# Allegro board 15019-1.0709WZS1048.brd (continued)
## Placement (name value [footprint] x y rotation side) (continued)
NOREF#2  *  [unnamed]  40.67 23.11 0 top
NOREF#3  -  [#2]  -10 0 0 top
NOREF#4  *  [unnamed]  62.77 66.55 0 top
NOREF#5  *  [unnamed]  72.55 202.69 0 top
NOREF#6  -  [unnamed]  11.57 4.95 0 top
NOREF#7  -  [unnamed]  184.44 225.3 0 top
NOREF#8  *  [unnamed]  169.06 9.9 0 top
NOREF#9  -  [#2]  96.43 126.87 0 top
NOREF#10  -  [unnamed]  149 223.77 0 top
NOREF#11  -  [#2]  -310 0 0 top
NOREF#12  -  [#2]  0 100.97 0 top
NOREF#13  *  [unnamed]  7.78 219.33 0 top
NOREF#14  -  [#2]  -10 0 0 top
NOREF#15  -  [unnamed]  6.64 225.3 0 top
NOREF#16  -  [#2]  -10 0 0 top
NOREF#17  -  [#2]  105.19 194.31 0 top
NOREF#18  -  [#2]  133.89 208.03 0 top
NOREF#19  *  [unnamed]  157.46 223.44 0 top
NOREF#20  *  [unnamed]  180.24 219.05 0 top
NOREF#21  *  [unnamed]  166.66 27.56 0 top
NOREF#22  -  [unnamed]  178.22 223.03 0 top
NOREF#23  *  [unnamed]  7.46 5.42 0 top
NOREF#24  -  [#2]  152.81 98.04 0 top
NOREF#25  -  [unnamed]  171.63 4.95 0 top
NOREF#26  -  [#2]  -10 0 0 top
NOREF#27  -  [unnamed]  6.64 9.4 0 top
NOREF#28  -  [#2]  120.05 156.34 90 bottom
NOREF#29  *  [unnamed]  40.17 24.64 180 bottom
NOREF#30  -  [#2]  178.7 28.65 90 bottom
NOREF#31  *  [unnamed]  169.06 9.9 180 bottom
NOREF#32  *  [unnamed]  45.37 223.77 180 bottom
NOREF#33  *  [unnamed]  157.46 223.44 180 bottom
NOREF#34  *  [unnamed]  7.46 5.42 180 bottom
NOREF#35  *  [unnamed]  180.24 219.05 180 bottom
NOREF#36  *  [unnamed]  49.56 123.7 180 bottom
PC1  SC1U10V2KX-1DLGP  [C402H22]  124.87 208.41 90 bottom
PC34  SCD1U10V2KX-5GP  [C402H22]  101.25 64.64 90 bottom
PC48  SCD1U10V2KX-5GP  [C402H22]  17.43 157.35 270 bottom
PC49  SC1U16V3KX-4DLGP  [C603H36]  164.5 207.9 90 top
PC50  SC10U6D3V5KX-4DLGP-U  [C805H58]  154.21 207.52 270 top
PC51  SCD1U50V3KX-DL-GP  [C603H35]  152.69 205.87 90 top
PC52  SC10U6D3V5KX-4DLGP-U  [C805H58]  158.91 207.14 270 top
PC96  SCD1U16V2KX-3DLGP  [C402H22]  105.95 6.99 0 top
PC126  SC22P50V2JN-4GP  [C402H22]  157.26 194.31 90 top
PC140  SC1U10V2KX-1DLGP  [C402H22]  39.66 8 0 bottom
PC2127  SC470P50V2KX-3DLGP  [C402H22]  152.81 17.02 270 top
PC4301  SC10P50V2JN-4DLGP  [C402H22]  35.21 64.39 90 top
PC4302  SCD1U50V3KX-DL-GP  [C603H35]  36.48 71.63 180 top
PC4303  SC2200P50V2KX-2DLGP  [C402H22]  36.48 71.5 0 bottom
PC4304  SC470P50V2KX-3DLGP  [C402H22]  35.21 61.34 90 top
PC4305  SC10P50V2JN-4DLGP  [C402H22]  35.21 65.28 90 top
PC4401  SC10U25V5KX-DL-GP  [C805H58]  34.86 71.27 0 bottom
PC4402  SCD1U50V3KX-DL-GP  [C603H35]  57.69 61.34 270 bottom
PC4403  SCD1U50V3KX-DL-GP  [C603H35]  59.09 62.61 270 bottom
PC4404  SCD1U50V3KX-DL-GP  [C603H35]  56.29 62.61 90 bottom
PC4405  SCD1U25V2KX-1-DL-GP  [C402H22]  42.63 54.79 90 top
PC4406  SC10U25V5KX-DL-GP  [C805H58]  43.21 53.34 270 bottom
PC4407  SC10U25V5KX-DL-GP  [C805H58]  43.21 53.34 90 top
PC4408  SC1U25V5KX-3-GP  [C805H58]  55.53 58.93 90 bottom
PC4426  SC1U25V3KX-1-GP  [C603H36]  73.06 53.72 90 bottom
PC4601  SC1KP50V2KX-1DLGP  [C402H22]  24.29 222.63 270 bottom
PC4602  SC1U25V3KX-1-DLGP  [C603H36]  32.01 220.47 0 top
PC4603  SC3300P50V2KX-1DLGP  [C402H22]  22.64 217.17 180 bottom
PC4605  SC1KP50V2KX-1DLGP  [C402H22]  34.96 224.03 0 bottom
PC4606  SC1KP50V2KX-1DLGP  [C402H22]  27.34 216.92 90 top
PC4607  SCD1U16V2KX-3DLGP  [C402H22]  26.83 224.03 180 bottom
PC4608  SC2D2U10V3KX-1DLGP-U  [C603H36]  31.4 215.52 180 top
PC4609  SCD01U50V2KX-1DLGP  [C402H22]  27.34 217.81 270 top
PC4610  SC330P50V2KX-3-DL-GP  [C402H22]  38.51 221.62 90 bottom
PC4611  SC2200P50V2KX-2DLGP  [C402H22]  38.51 219.58 90 bottom
PC4612  SC10P50V2JN-4DLGP  [C402H22]  36.99 220.09 180 bottom
PC4613  SC330P50V2KX-3-DL-GP  [C402H22]  37.5 215.52 90 bottom
PC4614  SCD01U50V2KX-1DLGP  [C402H22]  33.05 220.73 0 top
PC4615  SC680P50V2KX-2DLGP  [C402H22]  23.15 214.63 90 bottom
PC4616  SCD01U50V2KX-1DLGP  [C402H22]  33.05 218.69 270 top
PC4617  SC680P50V2KX-2DLGP  [C402H22]  37.5 214.63 270 bottom
PC4618  SC1KP50V2KX-1DLGP  [C402H22]  23.15 213.74 270 bottom
PC4619  SCD1U16V2KX-3DLGP  [C402H22]  35.97 220.73 180 top
PC4621  SC330P50V2KX-3-DL-GP  [C402H22]  21.75 221.11 180 bottom
PC4622  SC1KP50V2KX-1DLGP  [C402H22]  33.05 216.03 270 top
PC4623  SCD047U16V2KX-1-DL-GP  [C402H22]  37.5 214.63 90 top
PC4624  SC3300P50V2KX-1DLGP  [C402H22]  38.01 218.06 180 bottom
PC4626  SC2200P50V2KX-2DLGP  [C402H22]  22.26 218.57 270 bottom
PC4627  SC10P50V2JN-4DLGP  [C402H22]  23.66 219.07 180 bottom
PC4628  SCD047U16V2KX-1-DL-GP  [C402H22]  23.15 213.74 90 top
PC4701  SC10U25V6KX-4DL-GP  [C1206H71]  41.56 199.01 90 bottom
PC4702  SC10U25V6KX-4DL-GP  [C1206H71]  41.56 201.29 270 top
PC4703  SCD1U50V3KX-DL-GP  [C603H35]  41.44 199.52 270 top
PC4704  SCD22U25V3KX-DL-GP  [C603H36]  32.93 209.42 0 bottom
PC4705  SC10U25V6KX-4DL-GP  [C1206H71]  41.56 201.29 90 bottom
PC4706  SC1KP50V2KX-1DLGP  [C402H22]  42.45 195.2 180 top
PC4707  SC10U25V6KX-4DL-GP  [C1206H71]  27.85 201.19 270 bottom
PC4708  SC10U25V6KX-4DL-GP  [C1206H71]  27.85 201.17 90 top
PC4709  SCD1U50V3KX-DL-GP  [C603H35]  27.85 199.39 90 top
PC4710  SCD22U25V3KX-DL-GP  [C603H36]  28.74 209.42 0 bottom
PC4711  SC10U25V6KX-4DL-GP  [C1206H71]  27.85 199.01 270 bottom
PC4712  SC1KP50V2KX-1DLGP  [C402H22]  27.08 195.2 180 top
PC4713  SCD1U50V3KX-DL-GP  [C603H35]  29.75 164.59 90 top
PC4801  SC10U25V6KX-4DL-GP  [C1206H71]  26.07 157.86 0 top
PC4802  SCD1U16V2KX-3DLGP  [C402H22]  40.67 152.02 270 top
PC4803  SC1U10V2KX-1DLGP  [C402H22]  23.07 155.68 90 top
PC4804  SC1KP50V2KX-1DLGP  [C402H22]  17.43 156.46 270 bottom
PC4805  SC18P50V2JN-1DLGP  [C402H22]  13.62 154.18 180 top
PC4806  SCD1U50V3KX-DL-GP  [C603H35]  24.29 158.12 180 top
PC4807  SC1KP50V2KX-1DLGP  [C402H22]  33.18 156.84 270 top
PC4808  SC10U25V6KX-4DL-GP  [C1206H71]  26.07 157.86 180 bottom
PC4901  SCD01U50V2KX-1DLGP  [C402H22]  123.22 8.97 90 bottom
PC4902  SC10U25V6KX-4DL-GP  [C1206H71]  121.11 7.11 0 bottom
PC4903  SCD1U50V3KX-DL-GP  [C603H35]  115.6 10.16 180 top
PC4904  SC10U25V6KX-4DL-GP  [C1206H71]  120.48 23.24 180 bottom
PC4905  SCD01U50V2KX-1DLGP  [C402H22]  123.3 21.11 90 bottom
PC4906  SC1U10V2KX-1DLGP  [C402H22]  114.84 13.97 90 top
PC4907  SCD1U50V3KX-DL-GP  [C603H35]  112.05 6.22 0 top
PC4908  SCD1U50V3KX-DL-GP  [C603H35]  112.56 17.14 0 top
PC4909  SC1U10V2KX-1DLGP  [C402H22]  132.62 5.97 0 top
PC4910  SC1U10V2KX-1DLGP  [C402H22]  132.62 22.99 180 top
PC4911  SC22P50V2JN-4DLGP  [C402H22]  106.97 10.03 0 top
PC4912  SC1U16V3KX-4DLGP  [C603H36]  106.08 15.75 270 top
PC4913  SC22P50V2JN-4DLGP  [C402H22]  106.97 14.1 0 top
PC4914  SC4D7U6D3V3KX-DLGP  [C603H36]  115.22 14.99 270 top
PC4915  SC1500P50V3KX-DLGP  [C603H36]  122.92 20.09 90 bottom
PC4916  SC1500P50V3KX-DLGP  [C603H36]  122.84 10.01 90 bottom
PC4917  SC18P50V2JN-1DLGP  [C402H22]  106.46 14.1 90 bottom
PC4918  SC18P50V2JN-1DLGP  [C402H22]  106.46 10.03 90 bottom
PC5001  SC10U10V5KX-2DLGP  [C805H50]  136.05 80.77 270 top
PC5003  SC1KP50V2KX-1DLGP  [C402H22]  147.1 80.39 270 top
PC5009  SC1U10V2KX-1DLGP  [C402H22]  146.46 76.96 90 top
PC5010  SCD1U50V3KX-DL-GP  [C603H35]  144.31 83.57 0 top
PC5011  SC10U10V5KX-2DLGP  [C805H50]  137.32 83.95 180 top
PC5012  SC1U16V3KX-4DLGP  [C603H36]  143.29 104.01 0 top
PC5013  SC18P50V2JN-1DLGP  [C402H22]  139.99 74.04 90 top
PC5014  SCD033U25V3KX-DL-GP  [C603H36]  136.43 75.11 270 top
PC5016  SC10U10V5KX-2DLGP  [C805H50]  135.29 83.95 180 top
PC5017  SC1500P50V3KX-DLGP  [C603H36]  141.38 93.27 180 bottom
PC5018  SC1U10V2KX-1DLGP  [C402H22]  146.46 76.07 90 top
PC5019  SCD1U50V3KX-DL-GP  [C603H35]  138.84 92.58 270 bottom
PC5020  SC10U25V6KX-4DL-GP  [C1206H71]  138.84 88.52 270 bottom
PC5021  SC10U25V6KX-4DL-GP  [C1206H71]  138.84 90.81 270 bottom
PC5022  SC10U25V6KX-4DL-GP  [C1206H71]  138.84 88.52 90 top
PC5202  SC1500P50V3KX-DLGP  [C603H36]  107.22 66.8 270 bottom
PC5203  SC22P50V2JN-4DLGP  [C402H22]  101.25 61.59 90 top
PC5204  SC1U10V2KX-1DLGP  [C402H22]  101.25 64.64 270 top
PC5205  SC22U6D3V3MX-1-DL-GP  [C603H40]  103.03 77.34 180 top
PC5209  SC10U25V6KX-4DL-GP  [C1206H71]  106.97 58.55 90 top
PC5210  SC22U6D3V3MX-1-DL-GP  [C603H40]  104.3 77.34 180 top
PC5211  SC22U6D3V3MX-1-DL-GP  [C603H40]  105.57 77.34 180 top
PC5212  SC22U6D3V3MX-1-DL-GP  [C603H40]  101.76 77.34 180 top
PC5213  SCD1U16V2KX-3DLGP  [C402H22]  100.62 77.34 180 top
PC5214  SC10U25V6KX-4DL-GP  [C1206H71]  106.97 60.83 90 top
PC5217  SCD1U25V2KX-1-DL-GP  [C402H22]  101.25 66.67 90 top
PC5232  SCD01U50V2KX-1DLGP  [C402H22]  65.44 57.53 270 bottom
PC5233  SC1U10V2KX-1DLGP  [C402H22]  55.63 53.34 0 bottom
PC5234  SCD1U50V3KX-DL-GP  [C603H35]  55.91 57.23 270 bottom
PC5235  SC1KP50V2KX-1DLGP  [C402H22]  44.94 70.15 180 top
PC5236  SCD1U50V3KX-DL-GP  [C603H35]  60.99 49.78 270 bottom
PC5237  SC470P50V2KX-3DLGP  [C402H22]  58.86 51.99 180 bottom
PC5238  SCD1U25V2KX-1-DL-GP  [C402H22]  62.77 49.28 180 bottom
PC5239  SC220P50V2KX-3DLGP  [C402H22]  65.44 56.52 270 bottom
PC5240  SC10U25V5KX-DL-GP  [C805H58]  34.86 71.27 180 top
PC5241  SC10U25V5KX-DL-GP  [C805H58]  38.13 64.14 0 top
PC5242  SCD1U50V3KX-DL-GP  [C603H35]  39.78 64.26 0 top
PC5243  SC1U16V3KX-4DLGP  [C603H36]  18.96 147.83 270 top
PC5244  SC100P50V2JN-3DLGP  [C402H22]  31.28 143.26 0 top
PC5245  SCD1U10V2KX-5GP  [C402H22]  22 138.68 0 top
PC5246  SC1U16V3KX-4DLGP  [C603H36]  32.42 146.81 180 top
PC5247  SC10U10V5KX-2DLGP  [C805H50]  24.93 148.72 180 top
PC5248  SC10U10V5KX-2DLGP  [C805H50]  30.77 146.69 180 top
PC5401  SC10U25V6KX-4DL-GP  [C1206H71]  49.31 214.88 90 top
PC5402  SC10U25V6KX-4DL-GP  [C1206H71]  49.31 217.42 90 top
PC5403  SCD1U50V3KX-DL-GP  [C603H35]  49.94 216.03 270 bottom
PC5404  SC10U25V6KX-4DL-GP  [C1206H71]  42.22 212.57 270 top
PC5405  SC1KP50V2KX-1DLGP  [C402H22]  52.99 221.11 0 bottom
PC5411  SCD22U25V3KX-DL-GP  [C603H36]  71.66 213.74 270 bottom
PC5413  SC1KP50V2KX-1DLGP  [C402H22]  77.5 218.69 0 top
PC5414  SC1KP50V2KX-1DLGP  [C402H22]  75.09 222.88 180 bottom
PC5415  SC330P50V2KX-3-DL-GP  [C402H22]  82.84 223.9 180 bottom
PC5416  SC10P50V2JN-4DLGP  [C402H22]  81.95 222.88 180 bottom
PC5417  SC2200P50V2KX-2DLGP  [C402H22]  81.06 222.88 180 bottom
PC5418  SC1KP50V2KX-1DLGP  [C402H22]  84.74 219.2 180 bottom
PC5419  SC3300P50V2KX-1DLGP  [C402H22]  79.66 222.38 90 bottom
PC5420  SC1U25V3KX-1-DLGP  [C603H36]  85.63 214.38 270 bottom
PC5421  SC2D2U16V3KX-DL-GP  [C603H36]  76.49 209.17 180 bottom
PC5422  SCD1U10V2KX-5DLGP  [C402H22]  81.57 218.69 180 top
PC5423  SCD01U25V2KX-3DLGP  [C402H22]  79.54 218.69 180 top
PC5424  SCD01U25V2KX-3DLGP  [C402H22]  82.71 209.55 180 bottom
PC5425  SC680P50V2KX-2DLGP  [C402H22]  74.2 222.88 0 bottom
PC5426  SCD047U16V2KX-1-DL-GP  [C402H22]  71.66 221.49 270 bottom
PC5427  SC1U16V3KX-4DLGP  [C603H36]  154.97 208.79 270 bottom
PC5428  SC1U16V3KX-4DLGP  [C603H36]  154.97 213.11 270 bottom
PC5429  SC1U16V3KX-4DLGP  [C603H36]  151.04 212.85 90 bottom
PD4401  RB520SM-30T2R-GP  [D1608-035030AKH28]  54.24 54.48 0 bottom
PD4405  1N4148WS-7-F-GP  [SOD323AKH42]  72.8 63.75 270 bottom
PG4701  COPPER-CLOSE-GP-U  [CON2C-U]  40.29 185.17 0 top
PG4702  COPPER-CLOSE-GP-U  [CON2C-U]  40.29 178.82 180 top
PG4703  COPPER-CLOSE-GP-U  [CON2C-U]  29.12 185.17 0 top
PG4704  COPPER-CLOSE-GP-U  [CON2C-U]  29.12 178.82 180 top
PG4801  GAP-CLOSE-PWR-3-GP  [GAP-CLOSE-PWR-3]  40.67 151 0 top
PG4901  GAP-CLOSE-PWR-3-GP  [GAP-CLOSE-PWR-3]  115.1 13.08 0 top
PG4902  GAP-CLOSE-PWR-3-GP  [GAP-CLOSE-PWR-3]  136.94 5.08 90 top
PG4903  GAP-CLOSE-PWR-3-GP  [GAP-CLOSE-PWR-3]  136.94 24.26 90 top
PG4904  GAP-CLOSE-PWR-3-GP  [GAP-CLOSE-PWR-3]  114.71 16.13 0 top
PG4905  GAP-CLOSE-PWR-3-GP  [GAP-CLOSE-PWR-3]  58.58 48.26 0 top
PG4906  GAP-CLOSE-PWR-3-GP  [GAP-CLOSE-PWR-3]  47.66 65.79 270 bottom
PG4907  GAP-CLOSE-PWR-3-GP  [GAP-CLOSE-PWR-3]  58.58 47.32 0 top
PG4908  GAP-CLOSE-PWR-3-GP  [GAP-CLOSE-PWR-3]  49.18 65.79 270 bottom
PG5001  GAP-CLOSE-PWR-3-GP  [GAP-CLOSE-PWR-3]  134.15 107.7 270 top
PG5205  -  [GAP-CLOSE-PWR]  103.92 58.67 0 top
PG5210  -  [GAP-CLOSE-PWR]  103.92 57.91 0 top
PG5211  GAP-CLOSE-PWR-3-GP  [GAP-CLOSE-PWR-3]  99.35 76.58 180 top
PG5212  GAP-CLOSE-PWR-3-GP  [GAP-CLOSE-PWR-3]  106.97 76.58 0 top
PG5401  COPPER-CLOSE-GP-U  [CON2C-U]  59.22 211.46 0 top
PG5402  COPPER-CLOSE-GP-U  [CON2C-U]  59.22 205.1 180 top
PG9001  GAP-CLOSE-PWR-3-GP  [GAP-CLOSE-PWR-3]  59.27 98.09 0 top
PL4301  MLVS0402M04-GP-U  [L402H24]  35.21 62.36 90 top
PL4302  MLVS0402M04-GP-U  [L402H24]  35.21 66.29 90 top
PL4303  MLVS0402M04-GP-U  [L402H24]  35.21 63.37 90 top
PL4701  IND-D36UH-19-GP  [L115100-2H158]  40.29 181.99 0 top
PL4702  IND-D36UH-19-GP  [L115100-2H158]  29.12 181.99 0 top
PL4802  IND-1D5UH-53-GP  [L686647H119]  39.78 156.34 0 top
PL4903  IND-3D3UH-116-GP-U  [L686647-127318H119]  128.56 10.67 270 top
PL4904  IND-2D2UH-122-GP  [L686647H119]  128.68 18.29 0 top
PL5001  IND-D68UH-36-GP  [L686647H119]  138.84 102.23 90 top
PL5003  IND-5D6UH-48-GP-U1  [L7066-1830-UH119]  42.71 61.47 0 bottom
PL5202  IND-2D2UH-122-GP  [L686647H119]  103.16 71.6 90 top
PL5401  IND-D36UH-19-GP  [L115100-2H158]  59.22 208.28 0 top
PQ4204  PDTC124EU-1-GP  [SOT323CBE2D2H44]  67.47 36.96 270 bottom
PQ4205  PDTA124EU-1-GP  [SOT323CBE2D2H44]  67.34 33.4 180 bottom
PQ4206  2N7002K-2-GP  [SOT23DGS2D4H44]  67.22 40.39 180 bottom
PQ4406  2N7002KDW-GP  [SOT-363H44]  73.44 56.13 0 bottom
PQ4408  2N7002K-2-GP  [SOT23DGS2D4H44]  71.69 63.98 0 top
PQ4409  MMBT3906-4-GP  [SOT23CBE2D4H44]  72.55 60.83 0 bottom
PQ5003  2N7002A-7-GP  [SOT23DGS2D4H48]  71.69 67.79 0 top
PQ5004  2N7002A-7-GP  [SOT23DGS2D4H48]  66.81 63.96 0 top
PQ5005  NTJD512NT1G-GP  [SOT-363H44]  48.55 38.99 0 top
PQ5006  2N7002KDW-GP  [SOT-363H44]  62.39 65.28 0 bottom
PR24  0R0402-PAD-2-GP  [0R0402-PAD-1]  33.94 224.03 0 bottom
PR57  10KR2F-2-GP  [R402H16]  101.25 62.61 270 bottom
PR62  10KR2F-2-GP  [R402H16]  101.25 60.58 90 top
PR83  10R2F-L-GP  [R402H14]  17.18 163.45 90 top
PR190  10KR2J-3-GP  [R402H16]  106.97 6.99 0 top
PR4210  1KR2J-1-GP  [R402H16]  69.5 39.5 180 bottom
PR4214  3K3R6J-GP  [R1206H28]  67.22 30.23 270 bottom
PR4412  47KR2F-GP  [R402H16]  65.44 58.55 270 bottom
PR4413  100KR2F-L1-GP  [R402H16]  73.57 52.2 0 bottom
PR4425  3K3R2J-3-GP  [R402H16]  66.86 53.01 0 bottom
PR4426  3K3R2J-3-GP  [R402H16]  66.86 54.91 180 bottom
PR4427  100KR2J-1-GP  [R402H16]  65.95 60.83 90 bottom
PR4431  100KR2J-1-GP  [R402H16]  75.34 61.85 90 bottom
PR4433  1MR2J-1-GP  [R402H16]  75.34 60.83 270 bottom
PR4450  10KR2F-2-GP  [R402H16]  72.55 52.2 180 bottom
PR4451  680KR2F-GP  [R402H16]  75.34 59.82 270 bottom
PR4455  0R2J-2-GP  [R402H16]  75.47 56.64 0 bottom
PR4458  0R2J-2-GP  [R402H16]  74.2 65.41 270 bottom
PR4462  0R2J-2-GP  [R402H16]  73.06 58.42 270 bottom
PR4601  1KR2F-3-GP  [R402H16]  23.66 217.17 180 bottom
PR4602  2R2F-GP  [R402H16]  32.93 224.08 0 top
PR4603  10KR2F-2-GP  [R402H16]  24.67 209.17 180 bottom
PR4604  0R0402-PAD-2-GP  [0R0402-PAD-1]  23.78 224.03 0 bottom
PR4605  61K9R2F-GP  [R402H16]  27.85 224.03 180 bottom
PR4606  0R0402-PAD-2-GP  [0R0402-PAD-1]  24.8 224.03 0 bottom
PR4608  10KR2F-2-GP  [R402H16]  37.5 213.61 90 top
PR4609  27K4R2F-GP  [R402H16]  37.5 216.53 270 bottom
PR4610  54K9R2F-L-GP  [R402H16]  31.91 224.03 180 bottom
PR4611  100R2J-2-GP  [R402H14]  65.44 186.06 90 top
PR4612  10R2F-L-GP  [R402H14]  37.5 212.6 270 bottom
PR4613  NTC-100K-10-GP-U  [NTC-402H22-U]  51.21 196.34 180 top
PR4614  27K4R2F-GP  [R402H16]  27.34 218.82 90 top
PR4615  10KR2F-2-GP  [R402H16]  23.15 212.72 270 top
PR4616  1KR2F-3-GP  [R402H16]  36.36 222.66 270 top
PR4618  10R2F-L-GP  [R402H14]  23.15 211.71 90 bottom
PR4619  75KR2F-GP  [R402H16]  21.62 216.15 0 bottom
PR4620  165KR2F-GP  [R402H16]  23.15 215.65 90 top
PR4621  1KR2F-3-GP  [R402H16]  36.99 222.12 180 bottom
PR4622  49D9R2F-GP  [R402H16]  38.51 222.63 270 bottom
PR4623  8K2R2F-1-GP  [R402H16]  38.51 220.6 270 bottom
PR4624  10KR2F-2-GP  [R402H16]  28.86 224.03 180 bottom
PR4625  41K2R2F-GP  [R402H16]  38.26 213.61 270 bottom
PR4626  27K4R2F-GP  [R402H16]  23.15 215.65 90 bottom
PR4627  28K7R2F-GP  [R402H16]  33.05 217.04 270 top
PR4628  100R2J-2-GP  [R402H14]  65.44 187.2 90 top
PR4629  61K9R2F-GP  [R402H16]  34.96 220.73 180 top
PR4630  NTC-100K-10-GP-U  [NTC-402H22-U]  18.19 196.34 180 top
PR4631  0R2J-2-GP  [R402H16]  23.15 210.69 90 bottom
PR4632  10KR2F-2-GP  [R402H16]  29.88 224.03 180 bottom
PR4633  0R0402-PAD-2-GP  [0R0402-PAD-1]  37.5 211.58 270 bottom
PR4634  49D9R2F-GP  [R402H16]  23.15 221.62 90 bottom
PR4635  24KR2F-GP  [R402H16]  25.69 209.17 180 bottom
PR4636  1KR2F-3-GP  [R402H16]  23.15 220.6 90 bottom
PR4637  NTC-220K-GP-U  [NTC-402H22-U]  23.02 183.01 180 top
PR4638  1KR2F-3-GP  [R402H16]  36.99 218.06 180 bottom
PR4639  NTC-220K-GP-U  [NTC-402H22-U]  46.39 184.15 180 top
PR4640  75KR2F-GP  [R402H16]  39.02 218.06 0 bottom
PR4641  48D7KR2F-GP  [R402H16]  22.26 212.72 90 bottom
PR4642  0R0402-PAD-2-GP  [0R0402-PAD-1]  35.97 224.03 0 bottom
PR4643  100R2J-2-GP  [R402H14]  41.94 170.31 90 top
PR4644  300KR2F-GP  [R402H16]  37.5 216.53 270 top
PR4645  8K2R2F-1-GP  [R402H16]  22.26 219.58 90 bottom
PR4685  10R2F-L-GP  [R402H14]  72.17 222.88 0 bottom
PR4701  2D2R3-1-U-GP  [R603H22]  34.2 209.42 180 bottom
PR4702  2D2R6J-3-GP  [R1206H28]  42.96 191.9 180 top
PR4703  2D2R3-1-U-GP  [R603H22]  27.47 209.42 180 bottom
PR4704  2D2R6J-3-GP  [R1206H28]  26.45 191.9 180 top
PR4802  75KR2F-GP  [R402H16]  14.13 157.73 90 top
PR4803  11K8R2F-GP  [R402H16]  14.64 154.18 180 top
PR4805  10KR2J-3-GP  [R402H16]  15.53 159.38 0 top
PR4806  2D2R5J-1-GP  [R805H24]  30.39 156.34 270 top
PR4807  470KR2F-GP  [R402H16]  16.77 153.97 270 top
PR4812  2D2R3-1-U-GP  [R603H22]  23.53 160.15 90 top
PR4814  -  [0R0805-PAD]  25.31 163.07 90 top
PR4815  -  [0R0805-PAD]  25.31 165.1 90 top
PR4816  33KR2F-GP  [R402H16]  14.13 155.7 270 top
PR4901  100KR2J-1-GP  [R402H16]  114.46 10.16 180 top
PR4902  2D2R5J-1-GP  [R805H24]  110.4 6.22 180 top
PR4903  2D2R5J-1-GP  [R805H24]  110.9 17.65 180 top
PR4911  2D2R5J-1-GP  [R805H24]  127.08 9.55 90 bottom
PR4912  2D2R5J-1-GP  [R805H24]  127.16 20.47 90 bottom
PR4914  6K65R2F-GP  [R402H16]  105.95 10.03 180 top
PR4917  10KR2F-2-GP  [R402H16]  106.46 11.56 270 top
PR4918  56K2R2F-2-GP  [R402H16]  114.84 12.06 270 top
PR4919  68KR2F-GP  [R402H16]  106.46 12.06 90 bottom
PR4920  110KR2F-GP  [R402H16]  111.95 12.01 90 bottom
PR4921  15KR2F-GP  [R402H16]  105.95 14.1 180 top
PR4922  10KR2F-2-GP  [R402H16]  106.46 12.57 270 top
PR4924  249KR2F-GP  [R402H16]  106.46 11.05 90 bottom
PR4925  191KR2F-1-GP  [R402H16]  106.46 13.08 90 bottom
PR4927  -  [0R0805-PAD]  118.14 5.08 270 bottom
PR4929  -  [0R0805-PAD]  118.14 7.01 270 bottom
PR4930  -  [0R0805-PAD]  114.59 26.54 90 top
PR4931  -  [0R0805-PAD]  114.59 20.45 90 top
PR4932  -  [0R0805-PAD]  114.59 22.48 90 top
PR4933  -  [0R0805-PAD]  114.59 24.51 90 top
PR5002  5D1R2F-GP  [R402H16]  146.46 75.06 90 top
PR5003  10K5R2F-GP  [R402H16]  147.1 79.38 270 top
PR5004  -  [0R0603-PAD]  146.72 78.11 90 top
PR5005  10KR2F-2-GP  [R402H16]  145.98 72.62 180 top
PR5006  2D2R3-1-U-GP  [R603H22]  143.04 83.57 180 top
PR5007  620KR2F-GP  [R402H16]  144.94 73.53 180 top
PR5009  48D7KR2F-GP  [R402H16]  141.26 77.34 0 bottom
PR5018  -  [0R0805-PAD]  136.05 76.71 270 top
PR5019  -  [0R0805-PAD]  136.05 78.74 270 top
PR5020  -  [0R0805-PAD]  141.38 83.95 0 top
PR5021  -  [0R0805-PAD]  139.35 83.95 0 top
PR5023  40K2R2F-GP  [R402H16]  139.86 73.03 90 top
PR5032  -  [0R0805-PAD]  135.97 73.51 90 top
PR5034  2D2R5J-1-GP  [R805H24]  141.38 96.39 180 bottom
PR5201  20KR2F-L-GP  [R402H16]  101.25 62.61 90 top
PR5204  2D2R6J-3-GP  [R1206H28]  104.94 68.58 270 bottom
PR5205  2D2R3J-2-GP  [R603H22]  101.63 65.66 270 top
PR5206  10KR2F-2-GP  [R402H16]  111.41 64.39 270 top
PR5209  10KR2F-2-GP  [R402H16]  101.25 63.63 270 top
PR5223  10KR2F-2-GP  [R402H16]  101.25 63.63 90 bottom
PR5247  0R2J-2-GP  [R402H16]  40.55 20.07 180 top
PR5248  0R2J-2-GP  [R402H16]  39.53 20.07 180 top
PR5249  0R2J-2-GP  [R402H16]  43.59 20.07 180 top
PR5250  0R2J-2-GP  [R402H16]  42.58 20.07 180 top
PR5268  33KR2F-GP  [R402H16]  64.8 51.31 180 bottom
PR5269  D01R3721F-GP-U  [R3720H40]  48.42 63.63 270 bottom
PR5270  309KR2F-GP  [R402H16]  65.82 59.69 90 bottom
PR5272  49K9R2F-L-GP  [R402H16]  52.48 40.77 270 top
PR5273  100KR2J-1-GP  [R402H16]  69.35 66.6 180 top
PR5274  -  [0R0402-PAD]  65.82 51.31 180 bottom
PR5275  100KR2J-1-GP  [R402H16]  54.01 40.77 0 top
PR5276  D01R3721F-GP-U  [R3720H40]  55.28 46.86 180 top
PR5277  7D5R2F-GP  [R402H16]  61.5 51.31 180 bottom
PR5278  100KR2J-1-GP  [R402H16]  63.79 51.31 0 bottom
PR5279  1D5R2F-GP  [R402H16]  56.14 54.84 90 bottom
PR5281  100KR2J-1-GP  [R402H16]  69.35 64.62 0 top
PR5282  10KR2F-2-GP  [R402H16]  52.48 39.75 270 top
PR5283  10R2F-L-GP  [R402H14]  60.49 51.31 180 bottom
PR5284  20R5F-1GP  [R805H24]  55.53 58.93 90 top
PR5285  470KR2J-2-GP  [R402H16]  42.68 72.36 270 top
PR5286  10KR2F-2-GP  [R402H16]  62.64 51.31 180 bottom
PR5287  3D3MR2J-GP  [R402H16]  59.98 61.34 270 bottom
PR5288  -  [0R0402-PAD]  65.39 55.5 270 bottom
PR5289  100KR2J-1-GP  [R402H16]  70.52 61.09 180 top
PR5290  -  [0R0805-PAD]  22.89 148.72 0 top
PR5291  -  [0R0603-PAD]  33.69 144.78 270 top
PR5292  10KR2F-2-GP  [R402H16]  30.26 141.22 180 top
PR5293  8K87R2F-2-GP  [R402H16]  30.26 143.26 180 top
PR5294  2D2R5J-1-GP  [R805H24]  19.72 146.18 90 top
PR5295  10KR2F-2-GP  [R402H16]  19.85 144.65 90 top
PR5296  -  [0R0603-PAD]  33.69 143.38 270 top
PR5297  100KR2J-1-GP  [R402H16]  71.53 61.09 180 top
PR5298  120KR2F-L-GP  [R402H16]  69.25 62.48 180 top
PR5401  2D2R6J-3-GP  [R1206H28]  53.5 217.81 0 bottom
PR5402  34KR2F-GP  [R402H16]  78.52 218.69 0 top
PR5404  2D2R3-1-U-GP  [R603H22]  71.66 212.47 90 bottom
PR5407  49D9R2F-GP  [R402H16]  83.85 223.9 0 bottom
PR5408  10KR2F-2-GP  [R402H16]  71.15 222.88 0 bottom
PR5409  39KR2F-GP  [R402H16]  73.19 222.88 0 bottom
PR5410  100R2J-2-GP  [R402H14]  73.31 193.29 180 bottom
PR5411  27K4R2F-GP  [R402H16]  83.73 209.55 0 bottom
PR5412  24KR2F-GP  [R402H16]  76.11 216.92 90 top
PR5413  1KR2F-3-GP  [R402H16]  83.35 222.38 90 bottom
PR5414  NTC-220K-GP-U  [NTC-402H22-U]  65.31 209.3 0 top
PR5415  8K2R2F-1-GP  [R402H16]  81.44 224.41 90 bottom
PR5416  100R2J-2-GP  [R402H14]  72.3 193.29 180 bottom
PR5417  1KR2F-3-GP  [R402H16]  79.66 223.39 90 bottom
PR5418  2R2F-GP  [R402H16]  85.25 213.23 90 bottom
PR5419  10KR2F-2-GP  [R402H16]  76.11 217.93 90 top
PR5420  0R2J-2-GP  [R402H16]  86.14 219.71 270 bottom
PR5421  61K9R2F-GP  [R402H16]  80.55 218.69 180 top
PR5422  0R2J-2-GP  [R402H16]  86.14 218.69 270 bottom
PR5423  NTC-100K-20-GP  [NTC-402H24-U]  51.6 208.28 270 bottom
PR5424  1KR2F-3-GP  [R402H16]  81.69 209.55 0 bottom
PR5425  75KR2F-GP  [R402H16]  77.12 222.88 180 bottom
PR5426  165KR2F-GP  [R402H16]  76.11 222.88 180 bottom
PR5428  36KR2F-GP  [R402H16]  78.14 222.88 0 bottom
PR5429  10KR2F-2-GP  [R402H16]  73.82 218.57 0 top
PR5431  10KR2J-3-GP  [R402H16]  89.57 14.86 90 top
PR5463  10KR2F-2-GP  [R402H16]  85.25 215.52 90 bottom
PR5464  0R2J-2-GP  [R402H16]  80.68 209.55 180 bottom
PR5466  0R2J-2-GP  [R402H16]  85.25 216.53 270 bottom
PR5467  102KR2F-GP  [R402H16]  64.04 61.34 90 bottom
PR5468  110KR2F-GP  [R402H16]  64.04 62.36 270 bottom
PR5469  56K2R2F-2-GP  [R402H16]  62.52 61.85 180 bottom
PR5470  107KR2F-GP  [R402H16]  61.5 60.83 0 bottom
PR5472  4K99R2F-L-GP  [R402H16]  152.31 204.6 90 top
PR5473  6K49R2F-1-GP  [R402H16]  151.04 203.07 180 top
PR5475  2D2R3-1-U-GP  [R603H22]  164.5 206.63 270 top
PR8519  3K3R2J-3-GP  [R402H16]  95.16 58.8 270 bottom
PR8520  3K3R2J-3-GP  [R402H16]  95.16 59.82 270 bottom
PR8521  0R2J-2-GP  [R402H16]  85.5 55.12 90 bottom
PSWD1  JOWLE-CON2-5-GP  [A2541WV0-1EX2PA-6T]  153.2 114.43 270 top
PT4701  SE47U25VM-13-GP  [SE361414H241]  47.91 202.06 180 top
PT4702  E820U2D5VM-6-GP  [ECAP-100D6D3H375]  50.71 173.99 0 top
PT4703  E820U2D5VM-6-GP  [ECAP-100D6D3H375]  36.86 170.81 0 top
PT4704  E820U2D5VM-6-GP  [ECAP-100D6D3H375]  28.99 170.81 0 top
PT4708  E820U2D5VM-6-GP  [ECAP-100D6D3H375]  58.58 181.74 0 top
PT4709  E820U2D5VM-6-GP  [ECAP-100D6D3H375]  50.71 181.86 0 top
PT4712  SE47U25VM-13-GP  [SE361414H241]  21.5 202.06 180 top
PT4801  E820U2D5VM-6-GP  [ECAP-100D6D3H375]  48.17 152.53 0 top
PT4901  SE47U25VM-13-GP  [SE361414H241]  120.3 22.86 0 top
PT4902  SE220U6D3VM-8GP  [SE331721H237]  136.94 9.78 180 top
PT4903  SE220U6D3VM-8GP  [SE331721H237]  136.94 19.18 0 top
PT5007  E820U2D5VM-14-GP  [ECAP-100D6D3H355]  138.08 110.62 270 top
PT5401  E820U2D5VM-6-GP  [ECAP-100D6D3H375]  55.79 189.1 0 top
PT5402  E820U2D5VM-6-GP  [ECAP-100D6D3H375]  63.66 196.98 0 top
PT5403  E820U2D5VM-6-GP  [ECAP-100D6D3H375]  55.79 196.98 0 top
PT5405  SE47U25VM-13-GP  [SE361414H241]  43.11 218.44 180 top
PU4  AP2138N-1D5TRG1-GP  [SOT23-2D8-312H58]  158.15 120.14 0 top
PU5  APL5337KAI-TRG-GP  [SOIC8-G3530H63]  157.51 204.98 90 bottom
PU4403  AON7410-GP  [PPAK-8P-3232H36]  40.55 57.15 180 top
PU4405  AON7410-GP  [PPAK-8P-3232H36]  44.99 58.67 0 top
PU4601  NCP81128MNTXG-GP-U  [LFCSP52J6-G4D8H40]  30.39 217.81 180 bottom
PU4702  AON6520-GP  [PPAK-8P-5262H40]  22 194.18 0 top
PU4703  AON6510-GP  [PPAK-8P-5262H40]  30.89 192.41 0 bottom
PU4704  AON6510-GP  [PPAK-8P-5262H40]  30.89 192.41 180 top
PU4705  AON6510-GP  [PPAK-8P-5262H40]  38.51 192.41 180 top
PU4706  AON6510-GP  [PPAK-8P-5262H40]  38.51 192.41 0 bottom
PU4801  AON6510-GP  [PPAK-8P-5262H40]  32.16 152.02 270 top
PU4802  AON6520-GP  [PPAK-8P-5262H40]  30.39 160.66 90 top
PU4803  RT8237CZQW-2-GP  [DFN10G3-G265175H32]  18.7 156.84 90 top
PU4901  RT8243BZQW-GP  [QFN20-G1D75H32]  110.65 12.01 90 top
PU4902  AON7410-GP  [PPAK-8P-3232H36]  124.11 6.35 270 bottom
PU4903  AON7410-GP  [PPAK-8P-3232H36]  125.64 12.83 90 bottom
PU4904  AON7410-GP  [PPAK-8P-3232H36]  124.21 23.75 270 bottom
PU4905  AON7410-GP  [PPAK-8P-3232H36]  125.64 17.22 90 bottom
PU5001  RT8207MZQW-GP-U  [QFN20-G1D75H32]  142.02 78.36 90 top
PU5006  AON6520-GP  [PPAK-8P-5262H40]  136.56 92.84 180 top
PU5007  AON6510-GP  [PPAK-8P-5262H40]  143.16 94.61 0 top
PU5201  RT6220AGQUF-GP  [QFN16J3H24]  106.59 64.52 180 top
PU5204  AO4407AL-GP  [SOIC8H69]  58.2 42.04 270 top
PU5205  AO4407AL-GP  [SOIC8H69]  40.8 68.96 90 top
PU5206  APL5930KAI-TRG-1-GP  [SOIC8-G3530H63]  25.81 143.89 90 top
PU5207  AON6520-GP  [PPAK-8P-5262H40]  47.4 194.18 0 top
PU5401  AON6520-GP  [PPAK-8P-5262H40]  51.6 212.09 270 bottom
PU5402  AON6510-GP  [PPAK-8P-5262H40]  64.68 218.82 0 bottom
PU5403  AON6510-GP  [PPAK-8P-5262H40]  57.95 218.82 0 bottom
PU5407  NCP81128MNTXG-GP-U  [LFCSP52J6-G4D8H40]  78.77 215.77 90 bottom
PWRCN1  ACES-CON10-30-GP  [51530-01041-W01]  26.75 22.5 270 top
Q1  2N7002A-7-GP  [SOT23DGS2D4H48]  37.96 111.61 90 bottom
Q3  2N7002A-7-GP  [SOT23DGS2D4H48]  128.94 211.96 270 bottom
Q4  2N7002KDW-1-GP  [SOT-363H44]  36.15 75.59 270 bottom
Q5  2N7002A-7-GP  [SOT23DGS2D4H48]  37.96 115.21 90 bottom
Q7  2N7002KDW-1-GP  [SOT-363H44]  32.57 75.59 270 bottom
Q10  MMBT3904-4-GP  [SOT23CBE2D4H44]  34.07 118.11 180 bottom
Q12  MMBT3904DW-GP  [SOT-363H44]  41.82 76.53 270 bottom
Q13  MMBT3904DW-GP  [SOT-363H44]  46.26 75.9 90 bottom
Q14  SSM3K329R-1-GP  [SOT23DGS2D4H35]  18.45 165.86 0 top
Q18  2N7002KDW-1-GP  [SOT-363H44]  56.29 141.6 270 top
Q22  MMBT3904-4-GP  [SOT23CBE2D4H44]  44.99 28.7 90 top
Q24  AZ5125-02S-R7G-GP  [SOT23-2D4-312H46]  165.18 70 180 bottom
Q28  2N7002-11-GP  [SOT23DGS2D4H44]  164.63 66.98 0 top
Q31  MMBT3904-4-GP  [SOT23CBE2D4H44]  161.07 66.98 0 top
Q36  MMBT3904DW-GP  [SOT-363H44]  32.55 7.87 90 top
Q37  2N7002KDW-GP  [SOT-363H44]  134.4 57.78 180 top
Q38  MMBT3904-4-GP  [SOT23CBE2D4H44]  29.5 22.73 0 bottom
Q43  AO4468L-GP  [SOIC8H69]  88.93 28.96 0 top
Q44  AO3413L-GP  [SOT23DGS2D8H50]  41.94 6.99 180 bottom
Q45  MMBT3904-4-GP  [SOT23CBE2D4H44]  51.16 36.14 180 bottom
Q46  AZ5125-02S-R7G-GP  [SOT23-2D4-312H46]  84.11 42.16 270 top
Q47  2N7002A-7-GP  [SOT23DGS2D4H48]  57.77 36.14 0 bottom
Q50  PMBS3904-1-GP  [SOT-23-10H44]  93.76 222.88 0 top
Q51  2N7002A-7-GP  [SOT23DGS2D4H48]  19.34 223.14 90 bottom
Q52  MMBT3904-4-GP  [SOT23CBE2D4H44]  15.53 223.14 90 bottom
Q56  2N7002A-7-GP  [SOT23DGS2D4H48]  160.38 86.33 180 bottom
Q57  AZ5125-02S-R7G-GP  [SOT23-2D4-312H46]  165.51 76.58 270 bottom
Q63  MMBT3904DW-GP  [SOT-363H44]  141.64 30.68 270 top
Q64  2N7002A-7-GP  [SOT23DGS2D4H48]  143.49 34.09 270 top
Q65  2N7002KDW-1-GP  [SOT-363H44]  37.75 140.34 0 top
Q68  2N7002A-7-GP  [SOT23DGS2D4H48]  25.94 23.75 0 bottom
Q78  2N7002H-GP  [SOT23DGS2D4H44]  64.68 134.87 0 top
Q79  2N7002H-GP  [SOT23DGS2D4H44]  69.38 136.27 270 top
Q95  2N7002KDW-1-GP  [SOT-363H44]  53.5 71.63 90 top
Q100  MMBT3904-4-GP  [SOT23CBE2D4H44]  42.96 6.99 0 top
Q101  MMBT3904-4-GP  [SOT23CBE2D4H44]  47.53 6.99 0 top
Q102  MMBT3904-4-GP  [SOT23CBE2D4H44]  46.52 6.99 0 bottom
Q103  2N7002A-7-GP  [SOT23DGS2D4H48]  42.63 117.91 180 top
Q104  2N7002A-7-GP  [SOT23DGS2D4H48]  91.98 17.65 90 bottom
Q105  2N7002A-7-GP  [SOT23DGS2D4H48]  94.14 17.27 270 top
Q107  2N7002A-7-GP  [SOT23DGS2D4H48]  135.8 50.04 270 top
Q128  MMBT3904-4-GP  [SOT23CBE2D4H44]  128.94 215.65 270 bottom
Q1207  MMBT3904-4-GP  [SOT23CBE2D4H44]  107.98 159.26 90 bottom
Q1208  MMBT3904-4-GP  [SOT23CBE2D4H44]  73.19 135.25 270 top
Q1209  2N7002-11-GP  [SOT23DGS2D4H44]  77 135.25 270 top
Q1210  AO3413L-GP  [SOT23DGS2D8H50]  98.59 222.88 180 top
Q1211  AO3413L-GP  [SOT23DGS2D8H50]  125 205.87 0 bottom
Q1212  2N7002A-7-GP  [SOT23DGS2D4H48]  28.99 13.46 0 bottom
Q1213  MMBT3904-4-GP  [SOT23CBE2D4H44]  30.51 27.43 270 bottom
Q1214  MMBT3904-4-GP  [SOT23CBE2D4H44]  26.07 32.13 90 bottom
Q1217  2N7002KDW-1-GP  [SOT-363H44]  94.01 21.46 90 top
Q1226  2N7002KDW-1-GP  [SOT-363H44]  153.91 46.74 0 bottom
Q1227  2N7002H-GP  [SOT23DGS2D4H44]  162.85 41.02 180 top
Q1229  2N7002K-2-GP  [SOT23DGS2D4H44]  103.41 223.01 270 top
Q1240  2N7002-11-GP  [SOT23DGS2D4H44]  88.05 210.08 180 bottom
Q1241  MMBT3904-4-GP  [SOT23CBE2D4H44]  71.03 208.91 0 bottom
Q1243  2N7002-11-GP  [SOT23DGS2D4H44]  48.42 159.38 0 top
Q1244  2N7002-11-GP  [SOT23DGS2D4H44]  48.42 163.19 0 top
Q1245  2N7002-11-GP  [SOT23DGS2D4H44]  48.42 168.02 180 top
Q1246  2N7002H-GP  [SOT23DGS2D4H44]  59.98 135.51 270 top
Q1247  2N7002-11-GP  [SOT23DGS2D4H44]  51.98 168.02 180 top
Q1248  2N7002-11-GP  [SOT23DGS2D4H44]  51.98 163.19 180 top
Q1249  2N7002A-7-GP  [SOT23DGS2D4H48]  126.53 29.21 0 top
Q1250  AO4286-GP  [SOIC8H69]  43.14 45.75 270 bottom
Q4701  2N7002KDW-1-GP  [SOT-363H44]  151.16 210.06 270 top
Q6701  2N7002KDW-GP  [SOT-363H44]  82.08 64.54 0 top
Q6703  DMN2016LHAB-7-GP  [DFN6F2030-G1619H26]  156.12 210.95 270 bottom
Q6704  DMN2016LHAB-7-GP  [DFN6F2030-G1619H26]  156.12 215.26 270 bottom
Q9646  2N7002KDW-GP  [SOT-363H44]  25.69 13.08 0 bottom
Q9647  AO3413L-GP  [SOT23DGS2D8H50]  42.07 114.43 0 bottom
Q9648  2N7002A-7-GP  [SOT23DGS2D4H48]  86.01 57.53 90 bottom
Q9649  AO3413L-GP  [SOT23DGS2D8H50]  88.3 51.69 0 bottom
Q9650  2N7002A-7-GP  [SOT23DGS2D4H48]  42.07 119.38 0 bottom
Q90001  2N7002-11-GP  [SOT23DGS2D4H44]  115.48 92.08 180 top
Q90002  2N7002-11-GP  [SOT23DGS2D4H44]  110.65 92.2 0 top
R1  100KR2J-1-GP  [R402H16]  101 224.03 180 top
R5  10R2F-L-GP  [R402H14]  43.11 38.1 270 top
R8  330R3J-L-GP  [R603H22]  38.51 109.22 90 bottom
R10  8K2R2J-3-GP  [R402H16]  126.53 211.2 0 bottom
R12  10KR2J-3-GP  [R402H16]  157.26 195.33 90 top
R13  39K2R2F-L-GP  [R402H16]  125.51 211.2 180 bottom
R14  0R2J-2-GP  [R402H16]  122.08 220.47 270 top
R15  0R0402-PAD-2-GP  [0R0402-PAD-1]  131.48 212.6 0 bottom
R19  1MR2J-1-GP  [R402H16]  34.7 109.68 0 bottom
R20  470KR2F-GP  [R402H16]  38.77 119.38 270 bottom
R22  0R0402-PAD-2-GP  [0R0402-PAD-1]  104.17 215.14 270 top
R23  0R0402-PAD-2-GP  [0R0402-PAD-1]  104.17 216.15 270 top
R24  0R3J-0-U-GP  [R603H22]  158.53 194.44 180 bottom
R26  100KR2J-1-GP  [R402H16]  36.86 119.38 90 bottom
R27  D33R6F-GP  [R1206H26]  49.13 48.87 270 bottom
R30  100KR2J-1-GP  [R402H16]  36.86 118.36 90 bottom
R31  0R2J-2-GP  [R402H16]  23.02 139.57 180 top
R32  4K7R2J-2-GP  [R402H16]  39.94 86.49 0 bottom
R33  100KR2J-1-GP  [R402H16]  34.83 115.7 270 bottom
R35  0R0402-PAD-2-GP  [0R0402-PAD-1]  37.12 86.49 0 bottom
R37  0R1206-PAD-1-GP  [0R1206-PAD-1]  34.45 35.38 0 top
R39  22R2J-2-GP  [R402H16]  34.83 114.68 270 bottom
R41  10KR2J-3-GP  [R402H16]  33.82 113.67 90 bottom
R42  10KR2J-3-GP  [R402H16]  33.31 115.19 0 bottom
R43  0R0402-PAD-2-GP  [0R0402-PAD-1]  50.96 71.3 180 top
R45  100R2F-L1-GP-U  [R402H14]  34.96 31.88 180 bottom
R46  4K7R2J-2-GP  [R402H16]  35.09 86.49 0 bottom
R47  4K7R2J-2-GP  [R402H16]  31.53 85.09 270 bottom
R51  0R0402-PAD-2-GP  [0R0402-PAD-1]  30.89 41.15 90 top
R53  0R0402-PAD-2-GP  [0R0402-PAD-1]  30.89 40.13 90 top
R54  4K7R2J-2-GP  [R402H16]  56.8 72.14 0 top
R56  0R0402-PAD-2-GP  [0R0402-PAD-1]  31.53 37.08 90 top
R57  4K7R2J-2-GP  [R402H16]  39.12 74.32 270 top
R58  4K7R2J-2-GP  [R402H16]  31.53 84.07 270 bottom
R59  0R0402-PAD-2-GP  [0R0402-PAD-1]  31.53 36.07 90 top
R60  0R0402-PAD-2-GP  [0R0402-PAD-1]  38.13 72.39 90 top
R61  1KR2F-3-GP  [R402H16]  37.65 32.03 0 top
R65  0R5J-5-GP  [R805H24]  44.38 41.91 90 bottom
R68  100R2F-L1-GP-U  [R402H14]  11.46 217.68 0 top
R69  4K7R2J-2-GP  [R402H16]  52.74 73.66 270 top
R71  2K2R2J-2-GP  [R402H16]  12.61 217.68 0 top
R73  20KR2J-L2-GP  [R402H16]  15.91 207.01 180 top
R74  0R0402-PAD-2-GP  [0R0402-PAD-1]  16.92 207.01 180 top
R76  8K2R2F-1-GP  [R402H16]  15.91 208.91 180 top
R77  0R2J-2-GP  [R402H16]  101.25 61.59 90 bottom
R78  1KR2F-3-GP  [R402H16]  137.7 191.9 0 bottom
R80  4K7R2J-2-GP  [R402H16]  15.91 210.82 0 top
R81  0R2J-2-GP  [R402H16]  87.03 186.56 0 top
R82  10KR2F-2-GP  [R402H16]  33.94 31.88 180 bottom
R93  1KR2J-1-GP  [R402H16]  85 194.69 0 top
R99  0R0402-PAD-2-GP  [0R0402-PAD-1]  154.34 182.63 90 bottom
R101  -  [0R0805-PAD]  8.29 210.44 180 bottom
R107  150R2F-1-GP  [R402H16]  70.14 186.56 180 top
R110  0R2J-2-GP  [R402H16]  19.08 163.45 90 top
R111  100R2F-L1-GP-U  [R402H14]  165.64 128.91 90 top
R113  1MR3F-GP  [R603H22]  64.93 172.97 0 top
R115  1KR2F-3-GP  [R402H16]  95.28 166.37 90 bottom
R118  100KR2J-1-GP  [R402H16]  76.36 132.97 90 top
R119  100KR2J-1-GP  [R402H16]  78.27 132.97 90 top
R120  1KR2F-3-GP  [R402H16]  145.7 152.91 180 bottom
R121  39D2R2F-L-GP  [R402H16]  94.14 161.04 270 bottom
R122  1KR2F-3-GP  [R402H16]  147.61 150.88 180 bottom
R123  22R2J-2-GP  [R402H16]  79.28 143.51 180 top
R124  10KR2J-3-GP  [R402H16]  71.66 138.56 270 top
R125  0R2J-2-GP  [R402H16]  18.96 159.13 0 bottom
R131  0R2J-2-GP  [R402H16]  46.21 35.48 90 top
R132  100KR2J-1-GP  [R402H16]  45.22 32.36 270 top
R133  4K7R2J-2-GP  [R402H16]  46.21 34.44 270 top
R134  10KR2J-3-GP  [R402H16]  46.74 31.93 180 top
R135  4K7R2J-2-GP  [R402H16]  45.12 26.29 90 top
R137  10KR2J-3-GP  [R402H16]  60.74 156.08 180 top
R138  10KR2J-3-GP  [R402H16]  42.58 29.72 0 top
R139  4K7R2J-2-GP  [R402H16]  42.58 27.69 180 top
R143  1KR2J-1-GP  [R402H16]  45.12 25.27 270 top
R144  100KR2J-1-GP  [R402H16]  42.58 25.78 0 top
R152  10KR2J-3-GP  [R402H16]  82.84 140.84 90 top
R154  10KR2J-3-GP  [R402H16]  71.66 141.86 270 top
R159  10KR2J-3-GP  [R402H16]  83.47 137.16 90 top
R160  10KR2J-3-GP  [R402H16]  71.66 140.84 90 top
R162  2K2R2J-2-GP  [R402H16]  82.33 143.51 0 top
R163  10KR2J-3-GP  [R402H16]  130.34 129.29 90 bottom
R165  10KR2J-3-GP  [R402H16]  131.86 128.78 0 bottom
R171  470KR2F-GP  [R402H16]  57.56 144.27 0 top
R172  1MR2J-1-GP  [R402H16]  57.18 138.56 90 top
R174  0R0402-PAD-2-GP  [0R0402-PAD-1]  55.28 139.57 270 top
R175  10KR2J-3-GP  [R402H16]  57.18 139.57 270 top
R178  1KR2J-1-GP  [R402H16]  49.44 136.78 270 top
R179  100KR2J-1-GP  [R402H16]  56.04 144.78 270 top
R181  100KR2J-1-GP  [R402H16]  56.04 143.76 90 top
R183  -  [0R0805-PAD]  7.53 190.88 0 bottom
R184  10KR2J-3-GP  [R402H16]  153.07 109.6 270 top
R185  -  [0R0805-PAD]  5.49 190.88 0 bottom
R205  0R0402-PAD-2-GP  [0R0402-PAD-1]  157.64 88.52 90 top
R206  0R2J-2-GP  [R402H16]  162.21 86.87 270 top
R207  0R0402-PAD-2-GP  [0R0402-PAD-1]  165.44 87.05 0 top
R208  47KR2F-GP  [R402H16]  166.91 87.5 270 top
R209  33R2J-2-GP  [R402H16]  159.11 83.11 270 bottom
R210  47KR2F-GP  [R402H16]  166.91 86.49 90 top
R212  68R2F-GP  [R402H16]  158.02 83.13 180 top
R213  10KR2J-3-GP  [R402H16]  166.15 84.96 0 top
R215  0R0603-PAD-2-GP-U  [0R0603-PAD-1-U]  176.69 82.68 0 top
R216  0R3J-0-U-GP  [R603H22]  174.15 82.68 0 top
R220  10R2F-L-GP  [R402H14]  170.39 83.31 0 top
R221  10KR2J-3-GP  [R402H16]  171.41 83.31 180 top
R222  0R0402-PAD-2-GP  [0R0402-PAD-1]  157.64 81.66 90 top
R223  2K2R2J-2-GP  [R402H16]  168.94 83.44 90 top
R225  1KR2J-1-GP  [R402H16]  170.85 81.53 270 top
R261  2K2R2J-2-GP  [R402H16]  160.18 71.75 270 top
R262  2K2R2J-2-GP  [R402H16]  162.09 71.75 270 top
R266  10KR2F-2-GP  [R402H16]  164.5 71.25 180 top
R267  5K1R2F-2-GP  [R402H16]  165.51 71.25 180 top
R268  20KR2F-L-GP  [R402H16]  166.53 71.25 0 top
R272  2K2R2J-2-GP  [R402H16]  160.18 70.74 270 top
R276  -  [0R0603-PAD]  160.94 48.13 0 bottom
R281  10KR2J-3-GP  [R402H16]  162.09 69.72 90 top
R284  10R2F-L-GP  [R402H14]  160.18 69.72 90 top
R287  1KR2J-1-GP  [R402H16]  31.53 33.02 270 top
R289  10KR2J-3-GP  [R402H16]  162.09 53.59 90 top
R294  10KR2J-3-GP  [R402H16]  156.12 45.72 0 bottom
R297  1KR2J-1-GP  [R402H16]  162.09 54.61 90 top
R300  0R0603-PAD-2-GP-U  [0R0603-PAD-1-U]  162.34 68.71 0 bottom
R301  0R0603-PAD-2-GP-U  [0R0603-PAD-1-U]  162.85 75.56 180 bottom
R305  0R3J-0-U-GP  [R603H22]  162.21 48.13 180 bottom
R306  33R2J-2-GP  [R402H16]  162.09 55.63 90 top
R307  10KR2J-3-GP  [R402H16]  162.09 50.55 270 top
R308  10KR2J-3-GP  [R402H16]  162.09 58.67 90 top
R309  33R2J-2-GP  [R402H16]  162.09 59.69 270 top
R310  0R0402-PAD-2-GP  [0R0402-PAD-1]  157.26 64.14 180 top
R312  1KR2J-1-GP  [R402H16]  162.09 47.5 90 top
R313  10KR2J-3-GP  [R402H16]  163.61 45.97 180 top
R314  1KR2J-1-GP  [R402H16]  158.78 66.42 0 top
R316  10KR2J-3-GP  [R402H16]  162.09 44.45 90 top
R317  10KR2J-3-GP  [R402H16]  160.18 41.15 0 top
R319  100KR2F-L1-GP  [R402H16]  164.29 63.68 270 bottom
R322  1MR3F-GP  [R603H22]  163.96 62.59 90 bottom
R334  10KR2J-3-GP  [R402H16]  157.13 41.15 0 top
R341  10KR2J-3-GP  [R402H16]  156.12 41.15 0 top
R344  0R0603-PAD-2-GP-U  [0R0603-PAD-1-U]  158.15 24.51 0 top
R345  0R0603-PAD-2-GP-U  [0R0603-PAD-1-U]  161.32 37.85 270 top
R346  0R0603-PAD-2-GP-U  [0R0603-PAD-1-U]  163.36 31.5 0 top
R347  3K9R2F-GP  [R402H16]  164.37 27.56 0 top
R350  10KR2J-3-GP  [R402H16]  160.82 88.77 90 top
R351  10KR2J-3-GP  [R402H16]  150.66 56.01 180 bottom
R352  33R2J-2-GP  [R402H16]  153.96 64.14 180 top
R353  100KR2J-1-GP  [R402H16]  152.94 64.14 0 top
R355  10K5R3F-GP  [R603H22]  161.32 35.31 270 top
R356  0R0603-PAD-2-GP-U  [0R0603-PAD-1-U]  161.32 36.58 90 top
R357  10KR2F-2-GP  [R402H16]  160.56 27.05 180 top
R358  5K6R2F-2-GP  [R402H16]  162.09 29.59 90 top
R359  0R0603-PAD-2-GP-U  [0R0603-PAD-1-U]  158.15 21.72 0 top
R360  100KR2J-1-GP  [R402H16]  160.94 34.16 90 top
R361  100KR2J-1-GP  [R402H16]  160.56 29.08 180 top
R364  10KR2J-3-GP  [R402H16]  138.72 59.56 90 top
R365  10K5R3F-GP  [R603H22]  155.48 21.72 0 top
R366  1KR2J-1-GP  [R402H16]  131.86 56.52 90 top
R367  0R0603-PAD-2-GP-U  [0R0603-PAD-1-U]  156.75 21.72 180 top
R368  20KR2J-L2-GP  [R402H16]  131.86 59.56 90 top
R369  1KR2J-1-GP  [R402H16]  131.86 58.55 90 top
R370  1KR2J-1-GP  [R402H16]  138.72 62.61 270 top
R371  100R2F-L1-GP-U  [R402H14]  138.72 60.58 270 top
R372  0R0402-PAD-2-GP  [0R0402-PAD-1]  138.72 54.48 270 top
R373  0R0402-PAD-2-GP  [0R0402-PAD-1]  138.72 53.47 270 top
R374  0R0402-PAD-2-GP  [0R0402-PAD-1]  138.72 52.45 90 top
R375  0R0402-PAD-2-GP  [0R0402-PAD-1]  138.72 58.55 270 top
R376  10R3J-3-GP  [R603H22]  155.23 36.58 0 top
R377  1KR2J-1-GP  [R402H16]  27.64 6.17 0 bottom
R378  8K2R2J-3-GP  [R402H16]  33.31 5.59 270 top
R379  0R2J-2-GP  [R402H16]  138.72 57.53 90 top
R380  1KR2J-1-GP  [R402H16]  134.4 55.37 90 top
R381  10KR2J-3-GP  [R402H16]  134.91 61.21 270 top
R382  10KR2J-3-GP  [R402H16]  136.81 52.45 90 top
R383  0R0402-PAD-2-GP  [0R0402-PAD-1]  154.34 24.89 0 top
R384  1KR2J-1-GP  [R402H16]  134.91 60.2 270 top
R385  0R0402-PAD-2-GP  [0R0402-PAD-1]  138.72 55.5 90 top
R389  10KR5F-2-GP  [R805H24]  33.05 18.54 90 bottom
R396  3D3R3F-GP  [R603H22]  142.27 17.14 270 top
R397  10KR2F-2-GP  [R402H16]  146.69 50.5 90 bottom
R399  0R0402-PAD-2-GP  [0R0402-PAD-1]  146.69 51.54 270 bottom
R400  0R0402-PAD-2-GP  [0R0402-PAD-1]  146.69 48.39 270 bottom
R403  3D3R3F-GP  [R603H22]  144.94 17.14 90 top
R404  10KR2F-2-GP  [R402H16]  146.69 49.45 90 bottom
R406  1KR2J-1-GP  [R402H16]  32.8 8 180 bottom
R407  1MR3F-GP  [R603H22]  36.74 9.27 270 top
R412  2K49R2F-GP  [R402H16]  39.28 9.65 180 top
R413  0R2J-2-GP  [R402H16]  37.5 20.07 180 top
R415  3D3R3F-GP  [R603H22]  150.4 17.14 90 top
R419  3D3R3F-GP  [R603H22]  147.73 17.14 270 top
R428  47R2J-2-GP  [R402H16]  82.58 36.2 180 top
R429  47R2J-2-GP  [R402H16]  83.68 36.17 180 top
R433  1KR2J-1-GP  [R402H16]  107.98 16.89 90 top
R481  10KR2J-3-GP  [R402H16]  42.32 104.52 270 bottom
R482  10KR2J-3-GP  [R402H16]  44.48 95 180 bottom
R483  10KR2J-3-GP  [R402H16]  42.07 115.44 90 top
R484  100R2F-L1-GP-U  [R402H14]  42.2 111.89 270 bottom
R495  300R2J-4-GP  [R402H16]  85 190.63 0 top
R501  100KR2J-1-GP  [R402H16]  36.23 105.41 180 bottom
R502  0R0402-PAD-2-GP  [0R0402-PAD-1]  37.24 105.41 0 bottom
R503  0R2J-2-GP  [R402H16]  35.16 105.41 180 bottom
R504  100KR2J-1-GP  [R402H16]  96.17 223.9 180 top
R507  0R0402-PAD-2-GP  [0R0402-PAD-1]  31.53 99.75 270 bottom
R508  4K7R2J-2-GP  [R402H16]  20.23 220.73 90 top
R510  1KR2J-1-GP  [R402H16]  31.53 89.15 90 bottom
R511  12KR2F-L-GP  [R402H16]  31.53 98.73 90 bottom
R512  100KR2J-1-GP  [R402H16]  31.53 87.12 90 bottom
R513  100KR2J-1-GP  [R402H16]  44.23 79.17 90 top
R514  10KR2J-3-GP  [R402H16]  48.17 73 90 top
R515  0R0402-PAD-2-GP  [0R0402-PAD-1]  49.69 73.58 180 top
R517  10KR2J-3-GP  [R402H16]  31.53 90.17 270 bottom
R523  10KR2J-3-GP  [R402H16]  48.57 76.45 0 bottom
R524  10KR2J-3-GP  [R402H16]  41.44 80.34 180 bottom
R526  4K7R2J-2-GP  [R402H16]  17.86 220.17 270 top
R527  4K7R2J-2-GP  [R402H16]  15.4 220.85 270 bottom
R528  0R0402-PAD-2-GP  [0R0402-PAD-1]  73.82 190.63 180 top
R529  0R0402-PAD-2-GP  [0R0402-PAD-1]  74.84 190.63 180 top
R530  10KR2J-3-GP  [R402H16]  31.53 88.14 90 bottom
R531  10KR2J-3-GP  [R402H16]  46.46 73.48 0 top
R533  10KR2J-3-GP  [R402H16]  44.97 74.09 270 top
R535  4K7R2J-2-GP  [R402H16]  44.23 78.05 90 top
R536  0R0402-PAD-2-GP  [0R0402-PAD-1]  44.97 73.05 270 top
R542  1KR2J-1-GP  [R402H16]  45.37 127.38 270 top
R545  1KR2J-1-GP  [R402H16]  80.93 190.63 180 top
R557  1KR2F-3-GP  [R402H16]  59.09 174.24 180 top
R558  1K69R2F-2-GP  [R402H16]  58.07 174.24 0 top
R559  1KR2F-3-GP  [R402H16]  59.09 169.93 0 top
R568  0R0402-PAD-2-GP  [0R0402-PAD-1]  56.8 171.83 90 top
R570  10R2F-L-GP  [R402H14]  65.44 144.15 270 top
R571  10R2F-L-GP  [R402H14]  66.96 143.38 0 top
R576  0R0402-PAD-2-GP  [0R0402-PAD-1]  69.25 143.38 0 top
R582  10KR2J-3-GP  [R402H16]  62.26 155.7 270 top
R584  10R2F-L-GP  [R402H14]  63.03 145.8 0 top
R585  10R2F-L-GP  [R402H14]  65.44 145.16 270 top
R586  1KR2F-3-GP  [R402H16]  65.44 147.32 90 top
R617  33KR2J-3-GP  [R402H16]  165.18 85.45 180 bottom
R618  0R2J-2-GP  [R402H16]  158.02 87 0 bottom
R627  1KR2J-1-GP  [R402H16]  166.53 73.91 270 bottom
R634  4K7R2J-2-GP  [R402H16]  137.93 30.02 0 top
R635  1KR2J-1-GP  [R402H16]  138.31 31.5 90 top
R636  10KR2J-3-GP  [R402H16]  138.97 30.02 0 top
R637  10KR2J-3-GP  [R402H16]  143.95 29.21 180 top
R638  0R0402-PAD-2-GP  [0R0402-PAD-1]  147.78 34.92 90 top
R639  20KR2J-L2-GP  [R402H16]  146.51 33.43 180 top
R643  20KR2J-L2-GP  [R402H16]  147 31.5 0 top
R644  10KR2F-2-GP  [R402H16]  120.25 47.75 270 top
R645  10KR2F-2-GP  [R402H16]  131.68 48.01 90 top
R650  10KR2F-2-GP  [R402H16]  120.25 49.78 270 top
R651  0R0402-PAD-2-GP  [0R0402-PAD-1]  140.62 51.92 0 bottom
R655  10KR2F-2-GP  [R402H16]  120.25 50.8 270 top
R656  20KR2J-L2-GP  [R402H16]  152.81 50.03 90 bottom
R657  100KR2J-1-GP  [R402H16]  152.81 51.05 270 bottom
R658  10KR2F-2-GP  [R402H16]  142.88 50.42 90 bottom
R666  0R0402-PAD-2-GP  [0R0402-PAD-1]  156.88 31.5 90 bottom
R668  10KR2J-3-GP  [R402H16]  159.04 39.24 180 top
R674  0R0402-PAD-2-GP  [0R0402-PAD-1]  158.15 41.15 0 top
R675  10KR2J-3-GP  [R402H16]  159.16 41.15 0 top
R679  1KR2J-1-GP  [R402H16]  162.09 60.73 90 top
R680  10KR2J-3-GP  [R402H16]  156.24 64.14 180 top
R682  10KR2J-3-GP  [R402H16]  162.09 56.64 270 top
R683  10KR2J-3-GP  [R402H16]  149.89 64.26 0 top
R689  6K49R2F-1-GP  [R402H16]  139.1 47.12 90 bottom
R702  10KR2F-2-GP  [R402H16]  145.83 64.26 0 top
R707  0R0402-PAD-2-GP  [0R0402-PAD-1]  138.72 61.59 270 top
R709  0R0402-PAD-2-GP  [0R0402-PAD-1]  139.58 51.92 0 bottom
R715  0R2J-2-GP  [R402H16]  139.73 64.39 0 top
R716  0R2J-2-GP  [R402H16]  140.75 64.39 0 top
R717  10KR2J-3-GP  [R402H16]  66.96 135.76 180 top
R718  15KR2F-GP  [R402H16]  38.01 144.53 0 top
R722  1MR2J-1-GP  [R402H16]  35.21 140.21 90 top
R723  0R0402-PAD-2-GP  [0R0402-PAD-1]  28.56 14.45 180 top
R724  75R3F-GP  [R603H22]  28.35 19.94 270 bottom
R729  0R2J-2-GP  [R402H16]  25.05 16.13 90 bottom
R730  75R3F-GP  [R603H22]  25.69 21.21 270 bottom
R731  4K7R2J-2-GP  [R402H16]  24.67 26.67 180 bottom
R732  100KR2J-1-GP  [R402H16]  40.04 139.32 0 top
R733  100KR2J-1-GP  [R402H16]  40.04 141.22 0 top
R735  75R3F-GP  [R603H22]  25.69 19.94 90 bottom
R742  1KR2F-3-GP  [R402H16]  34.58 25.78 90 top
R743  33R2J-2-GP  [R402H16]  32.67 22.61 270 top
R744  -  [0R0402-PAD]  34.96 24.77 90 top
R755  4K7R2J-2-GP  [R402H16]  33.43 28.07 0 top
R758  33R2J-2-GP  [R402H16]  31.4 28.07 0 top
R762  15KR2F-GP  [R402H16]  106.59 29.59 0 top
R764  10KR2J-3-GP  [R402H16]  49.82 5.97 0 bottom
R774  10KR2J-3-GP  [R402H16]  44.23 7.87 180 bottom
R775  8K2R2J-3-GP  [R402H16]  47.02 9.4 90 top
R776  39K2R2F-L-GP  [R402H16]  45.25 7.87 0 top
R777  1KR2J-1-GP  [R402H16]  60.74 157.99 180 top
R1074  100KR2J-1-GP  [R402H16]  31.53 91.19 90 bottom
R1079  100KR2J-1-GP  [R402H16]  31.53 94.11 270 bottom
R1154  0R2J-2-GP  [R402H16]  106.71 203.58 270 top
R1155  0R2J-2-GP  [R402H16]  104.17 218.19 270 top
R1163  1KR2F-3-GP  [R402H16]  42.32 106.55 270 bottom
R1178  10KR2J-3-GP  [R402H16]  40.8 130.05 0 top
R1179  1KR2J-1-GP  [R402H16]  41.44 128.14 180 top
R1180  0R2J-2-GP  [R402H16]  48.8 5.97 180 bottom
R1182  0R0603-PAD-2-GP-U  [0R0603-PAD-1-U]  85 42.8 90 bottom
R1183  10KR2J-3-GP  [R402H16]  40.67 5.97 0 top
R1184  0R2J-2-GP  [R402H16]  59.22 148.84 270 top
R1185  10KR2J-3-GP  [R402H16]  93.63 14.86 180 bottom
R1186  10KR2J-3-GP  [R402H16]  88.43 17.14 0 top
R1188  10KR2J-3-GP  [R402H16]  162.09 52.58 90 top
R1193  0R0603-PAD-2-GP-U  [0R0603-PAD-1-U]  173.39 84.07 90 bottom
R1194  10KR2J-3-GP  [R402H16]  40.67 7.87 0 top
R1199  0R0402-PAD-2-GP  [0R0402-PAD-1]  158.02 39.24 180 top
R1203  0R0402-PAD-2-GP  [0R0402-PAD-1]  152.81 18.03 270 top
R1209  0R0402-PAD-2-GP  [0R0402-PAD-1]  106.71 204.6 270 top
R1584  1KR2J-1-GP  [R402H16]  96.05 161.04 270 bottom
R1585  0R2J-2-GP  [R402H16]  108.62 156.46 0 bottom
R1586  1KR2J-1-GP  [R402H16]  107.48 156.46 0 bottom
R1588  1KR2F-3-GP  [R402H16]  95.28 165.35 270 bottom
R1592  36R3F-GP  [R603H22]  132.75 43.94 0 top
R1593  4K7R2F-GP  [R402H16]  131.72 41.54 0 top
R1594  4K7R2F-GP  [R402H16]  126.91 42.55 0 top
R1595  0R3J-0-U-GP  [R603H22]  87.16 136.4 180 top
R1596  4K7R2F-GP  [R402H16]  131.85 29.6 180 top
R1598  4K7R2F-GP  [R402H16]  133.75 41.54 0 top
R1601  0R0603-PAD-2-GP-U  [0R0603-PAD-1-U]  88.43 136.4 0 top
R1603  2KR2F-3-GP  [R402H16]  72.17 186.56 180 top
R1604  1KR2J-1-GP  [R402H16]  71.15 186.56 180 top
R1605  1KR2J-1-GP  [R402H16]  74.2 186.56 180 top
R1606  1KR2J-1-GP  [R402H16]  73.19 186.56 180 top
R1607  1KR2J-1-GP  [R402H16]  75.22 186.56 180 top
R1608  1KR2J-1-GP  [R402H16]  77.88 186.56 180 top
R1609  1KR2J-1-GP  [R402H16]  76.87 186.56 180 top
R1610  1KR2J-1-GP  [R402H16]  81.95 190.63 180 top
R1611  0R0402-PAD-2-GP  [0R0402-PAD-1]  75.85 190.63 180 top
R1612  0R0402-PAD-2-GP  [0R0402-PAD-1]  69.76 190.63 180 top
R1613  0R0402-PAD-2-GP  [0R0402-PAD-1]  76.87 190.63 180 top
R1614  1KR2J-1-GP  [R402H16]  82.96 186.56 0 top
R1615  1KR2J-1-GP  [R402H16]  78.9 194.69 0 top
R1616  1KR2J-1-GP  [R402H16]  83.98 194.69 0 top
R1617  300R2J-4-GP  [R402H16]  79.92 186.56 0 top
R1618  1KR2J-1-GP  [R402H16]  77.88 197.99 180 top
R1619  1KR2J-1-GP  [R402H16]  76.87 197.99 180 top
R1620  0R2J-2-GP  [R402H16]  122.08 218.44 270 top
R1621  0R2J-2-GP  [R402H16]  122.08 217.42 270 top
R1622  0R2J-2-GP  [R402H16]  122.08 219.46 270 top
R1623  300R2J-4-GP  [R402H16]  88.04 190.63 180 top
R1628  1KR2J-1-GP  [R402H16]  79.92 190.63 180 top
R1629  0R2J-2-GP  [R402H16]  77.88 190.63 0 top
R1630  1KR2J-1-GP  [R402H16]  86.01 194.69 180 top
R1631  0R2J-2-GP  [R402H16]  88.04 194.69 0 top
R1632  1KR2J-1-GP  [R402H16]  80.93 186.56 180 top
R1633  1KR2F-3-GP  [R402H16]  142.4 191.9 180 bottom
R1634  10KR2J-3-GP  [R402H16]  131.61 126.24 270 bottom
R1635  10KR2J-3-GP  [R402H16]  133.51 126.24 270 bottom
R1644  1KR2F-3-GP  [R402H16]  64.8 148.46 90 top
R1645  22R2J-2-GP  [R402H16]  76.82 147.19 180 bottom
R1646  22R2J-2-GP  [R402H16]  80.93 137.16 270 top
R1647  0R0402-PAD-2-GP  [0R0402-PAD-1]  78.39 150.88 180 bottom
R1648  11K8R2F-GP  [R402H16]  71.79 154.56 90 bottom
R1649  1KR2F-3-GP  [R402H16]  65.44 170.43 270 top
R1650  1KR2J-1-GP  [R402H16]  65.44 143.13 90 top
R1653  0R0402-PAD-2-GP  [0R0402-PAD-1]  56.8 162.69 90 top
R1654  0R0402-PAD-2-GP  [0R0402-PAD-1]  62.26 154.69 90 top
R1657  1KR2F-3-GP  [R402H16]  74.2 142.11 0 top
R1658  15KR2F-GP  [R402H16]  56.68 163.7 90 top
R1659  10KR2J-3-GP  [R402H16]  84.74 141.86 90 top
R1660  10KR2J-3-GP  [R402H16]  84.74 140.84 270 top
R1661  10KR2J-3-GP  [R402H16]  75.22 142.11 180 top
R1662  10KR2J-3-GP  [R402H16]  82.84 141.86 270 top
R1663  10KR2J-3-GP  [R402H16]  76.23 142.11 0 top
R1664  1KR2J-1-GP  [R402H16]  56.68 164.72 90 top
R1665  1KR2J-1-GP  [R402H16]  56.8 161.67 90 top
R1666  1KR2J-1-GP  [R402H16]  62.26 157.73 90 top
R1668  0R0402-PAD-2-GP  [0R0402-PAD-1]  60.87 137.79 270 top
R1669  2K2R2J-2-GP  [R402H16]  80.3 143.51 0 top
R1670  10KR2J-3-GP  [R402H16]  60.1 153.67 90 top
R1671  20MR3-GP  [R603H22]  64.8 150.88 0 top
